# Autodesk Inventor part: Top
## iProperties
Created: 2010-01
Part Number: Top
Document SubType Name: Modeling
Designer: jgehrig
Density: 1 g/cm^3
Author: jgehrig
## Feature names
1. Extrusion1
2. Fillet1
3. Shell1
4. Fillet2
5. Extrusion2
6. Extrusion3
7. Extrusion4
